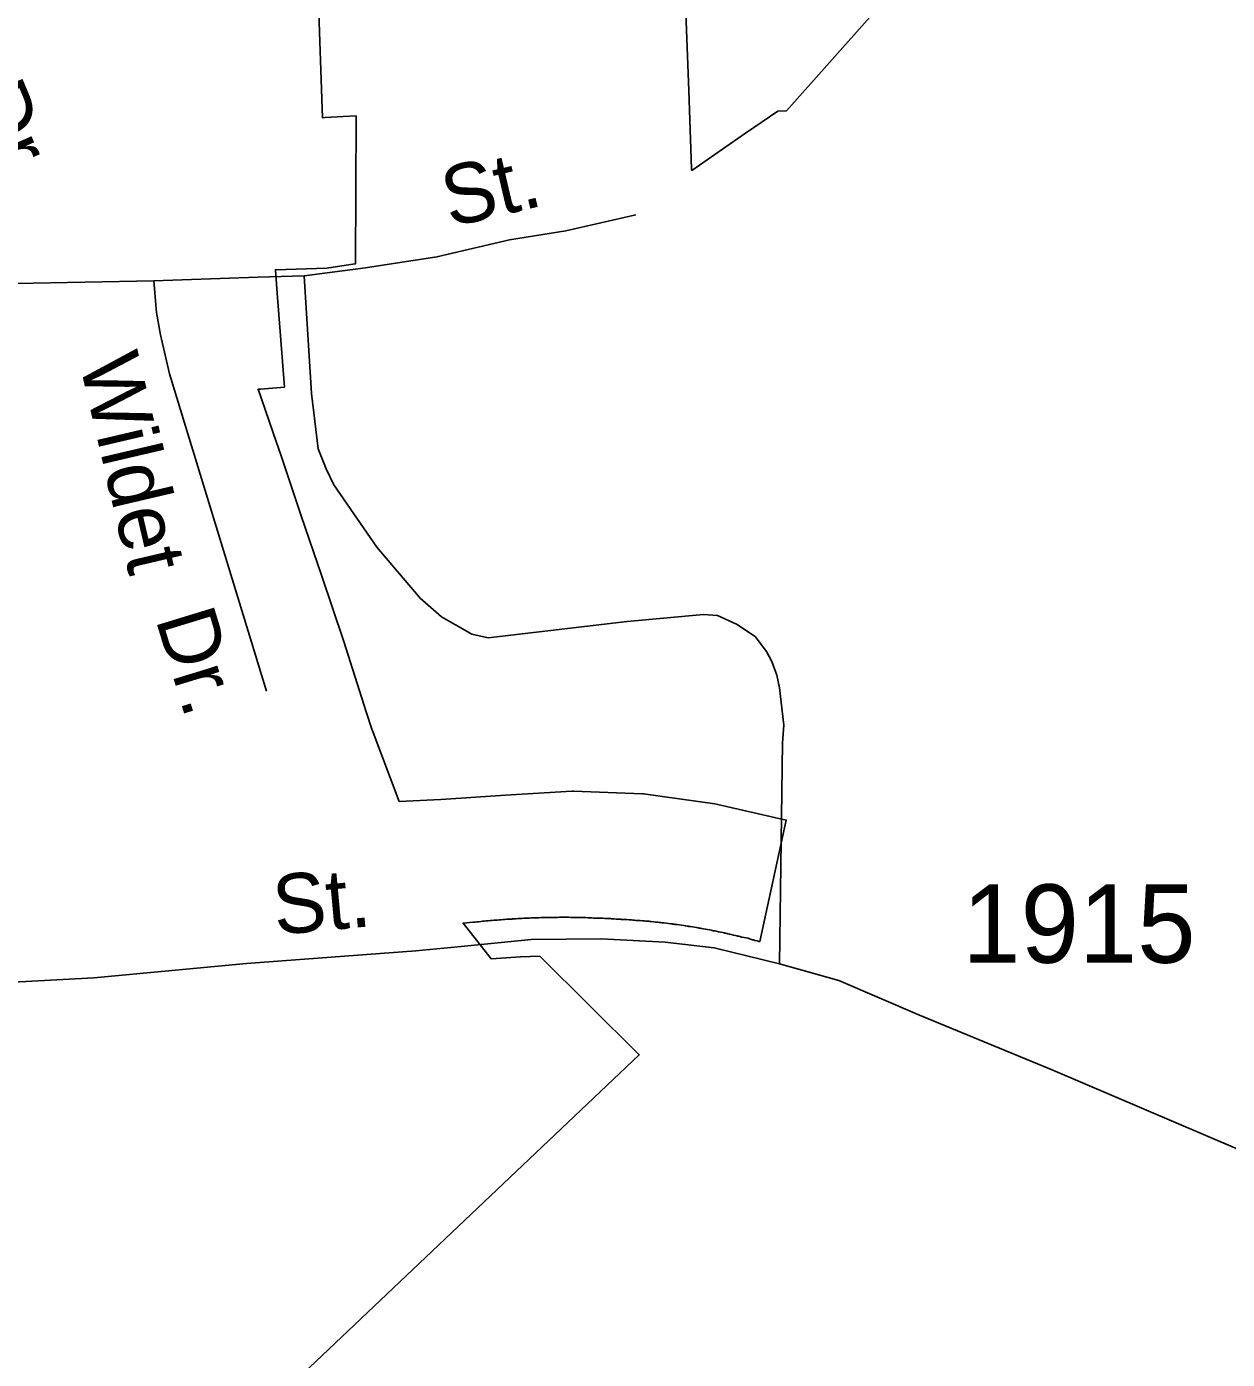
# Model space of a CAD drawing. Extents: x 2220236 to 2384410, y 720751 to 894131.
# Drawn here: x 2265814 to 2267728, y 799079 to 801203 of the extents above; entities that cross this region are included whole.
import ezdxf

# ---------------------------------------------------------------- set-up
doc = ezdxf.new("R2010")
doc.units = 0
doc.layers.add('Default', color=7, linetype='Continuous')

msp = doc.modelspace()

# ---------------------------------------------------------------- linework, layer by layer
at = {"layer": 'Default'}
msp.add_line((2265796.7, 800794), (2266016.6, 800798.2), dxfattribs=at)
for points in [[(2267702.2, 801830.4), (2267025, 801069), (2267011.5, 801068.7), (2266960, 801033.4), (2266874.2, 800974.4), (2266874, 800976.7), (2266869.5, 801101.6), (2266863, 801267.6)], [(2267702.2, 801830.4), (2267025, 801069), (2267011.5, 801068.7), (2266960, 801033.4), (2266874.2, 800974.4), (2266874, 800976.7), (2266869.5, 801101.6), (2266863, 801267.6)], [(2266263.5, 801697.6), (2266285.5, 801058.1), (2266289.8, 801058.4), (2266318.5, 801060.2), (2266339.2, 801061.4)], [(2266263.5, 801697.6), (2266285.5, 801058.1), (2266289.8, 801058.4), (2266318.5, 801060.2), (2266339.2, 801061.4)], [(2266339.2, 801061.4), (2266338.5, 800825.5), (2266337, 800825.2), (2266292.8, 800818.3), (2266210.5, 800816), (2266212.8, 800785.7), (2266225.2, 800629.1), (2266186.8, 800625.9), (2266183, 800625.6), (2266212, 800542.1), (2266220, 800519.6), (2266251.8, 800423.7), (2266284, 800329.1), (2266319.8, 800223.7), (2266355.5, 800111.5), (2266364.5, 800083.8), (2266366.5, 800078.6), (2266408, 799968.6), (2266474.5, 799971.9), (2266577.5, 799978.4), (2266683, 799985.1), (2266686, 799985.2), (2266795.8, 799980.9), (2266797.5, 799980.9), (2266911, 799964.5), (2267024.8, 799938.9), (2266982.5, 799745.1), (2266981.2, 799745.4), (2266978.5, 799746.3), (2266974.5, 799747.2), (2266972.5, 799747.8), (2266971.2, 799748.1), (2266969.5, 799748.6), (2266967.8, 799749.1), (2266966.5, 799749.4), (2266964, 799750.4), (2266961, 799751.1), (2266957.8, 799751.6), (2266954.2, 799752.4), (2266952.2, 799752.9), (2266950.8, 799753.3), (2266949.2, 799753.7), (2266947.5, 799754.1), (2266946.2, 799754.4), (2266944, 799754.9), (2266940.8, 799755.7), (2266937.2, 799756.5), (2266934.8, 799757.1), (2266933.8, 799757.2), (2266931.8, 799757.7), (2266930.5, 799758), (2266928.8, 799758.4), (2266927, 799758.8), (2266925.8, 799759), (2266923.5, 799759.5), (2266920.2, 799760.2), (2266916.8, 799760.9), (2266913.2, 799761.6), (2266911, 799762.1), (2266909.8, 799762.3), (2266908.2, 799762.6), (2266906.5, 799763), (2266905.2, 799763.2), (2266903, 799763.7), (2266899.5, 799764.3), (2266896, 799764.9), (2266892.8, 799765.6), (2266890.5, 799766), (2266889.2, 799766.2), (2266887.8, 799766.4), (2266885.8, 799766.8), (2266884.5, 799767), (2266882.2, 799767.4), (2266878.8, 799768), (2266875.5, 799768.6), (2266872, 799769.1), (2266869.8, 799769.5), (2266868.5, 799769.7), (2266866.8, 799769.9), (2266865, 799770.2), (2266863.8, 799770.4), (2266861.5, 799770.8), (2266858, 799771.2), (2266854.8, 799771.8), (2266851.2, 799772.2), (2266849, 799772.5), (2266847.8, 799772.7), (2266846, 799772.9), (2266844.2, 799773.2), (2266843, 799773.3), (2266840.8, 799773.6), (2266837.2, 799774.1), (2266833.8, 799774.5), (2266830.2, 799774.9), (2266828, 799775.2), (2266826.8, 799775.3), (2266825, 799775.5), (2266823.5, 799775.7), (2266822.2, 799775.8), (2266820, 799776.1)], [(2266339.2, 801061.4), (2266338.5, 800825.5), (2266337, 800825.2), (2266292.8, 800818.3), (2266210.5, 800816), (2266212.8, 800785.7), (2266225.2, 800629.1), (2266186.8, 800625.9), (2266183, 800625.6), (2266212, 800542.1), (2266220, 800519.6), (2266251.8, 800423.7), (2266284, 800329.1), (2266319.8, 800223.7), (2266355.5, 800111.5), (2266364.5, 800083.8), (2266366.5, 800078.6), (2266408, 799968.6), (2266474.5, 799971.9), (2266577.5, 799978.4), (2266683, 799985.1), (2266686, 799985.2), (2266795.8, 799980.9), (2266797.5, 799980.9), (2266911, 799964.5), (2267024.8, 799938.9), (2266982.5, 799745.1), (2266981.2, 799745.4), (2266978.5, 799746.3), (2266974.5, 799747.2), (2266972.5, 799747.8), (2266971.2, 799748.1), (2266969.5, 799748.6), (2266967.8, 799749.1), (2266966.5, 799749.4), (2266964, 799750.4), (2266961, 799751.1), (2266957.8, 799751.6), (2266954.2, 799752.4), (2266952.2, 799752.9), (2266950.8, 799753.3), (2266949.2, 799753.7), (2266947.5, 799754.1), (2266946.2, 799754.4), (2266944, 799754.9), (2266940.8, 799755.7), (2266937.2, 799756.5), (2266934.8, 799757.1), (2266933.8, 799757.2), (2266931.8, 799757.7), (2266930.5, 799758), (2266928.8, 799758.4), (2266927, 799758.8), (2266925.8, 799759), (2266923.5, 799759.5), (2266920.2, 799760.2), (2266916.8, 799760.9), (2266913.2, 799761.6), (2266911, 799762.1), (2266909.8, 799762.3), (2266908.2, 799762.6), (2266906.5, 799763), (2266905.2, 799763.2), (2266903, 799763.7), (2266899.5, 799764.3), (2266896, 799764.9), (2266892.8, 799765.6), (2266890.5, 799766), (2266889.2, 799766.2), (2266887.8, 799766.4), (2266885.8, 799766.8), (2266884.5, 799767), (2266882.2, 799767.4), (2266878.8, 799768), (2266875.5, 799768.6), (2266872, 799769.1), (2266869.8, 799769.5), (2266868.5, 799769.7), (2266866.8, 799769.9), (2266865, 799770.2), (2266863.8, 799770.4), (2266861.5, 799770.8), (2266858, 799771.2), (2266854.8, 799771.8), (2266851.2, 799772.2), (2266849, 799772.5), (2266847.8, 799772.7), (2266846, 799772.9), (2266844.2, 799773.2), (2266843, 799773.3), (2266840.8, 799773.6), (2266837.2, 799774.1), (2266833.8, 799774.5), (2266830.2, 799774.9), (2266828, 799775.2), (2266826.8, 799775.3), (2266825, 799775.5), (2266823.5, 799775.7), (2266822.2, 799775.8), (2266820, 799776.1)], [(2266256.4, 800806.4), (2266354.3, 800819.2), (2266468, 800836.3), (2266583.7, 800863.5), (2266673.6, 800878.2), (2266785.3, 800903.3)], [(2266016.6, 800798.2), (2266182.8, 800803.9), (2266256.4, 800806.4)], [(2266256.4, 800806.4), (2266268.2, 800618.7), (2266278.9, 800530.7), (2266291.3, 800498.8), (2266303.5, 800473), (2266372.5, 800373.6), (2266441.2, 800292.4), (2266475.3, 800262.7), (2266523.6, 800235.1), (2266549.6, 800229.4), (2266771.3, 800255.4), (2266893.1, 800266.6), (2266915.2, 800264.8), (2266945.4, 800251.2), (2266975.5, 800231.4), (2266993.6, 800207.6), (2267001.9, 800191.6), (2267010, 800169.7), (2267014.2, 800149.8), (2267020.8, 800089.9), (2267019, 800061.9), (2267014.3, 799709.9)], [(2266016.6, 800798.2), (2266021.1, 800748.1), (2266027.4, 800712.2), (2266041.9, 800650.3), (2266196.6, 800144.1)], [(2266813, 799776.8), (2266809.5, 799777.2), (2266807.2, 799777.4), (2266806, 799777.5), (2266804.2, 799777.7), (2266802.5, 799777.8), (2266801.2, 799777.9), (2266799, 799778.1), (2266795.5, 799778.4), (2266792, 799778.7), (2266788.5, 799779), (2266785.5, 799778.8), (2266783.2, 799779.2), (2266781.5, 799779.5), (2266780.2, 799779.6), (2266778, 799779.8), (2266774.5, 799780), (2266771, 799780.2), (2266768.5, 799780.3), (2266767.5, 799780.4), (2266765.5, 799780.5), (2266764, 799780.6), (2266762.5, 799780.6), (2266760.5, 799780.8), (2266759.5, 799780.8), (2266756.5, 799781), (2266753.5, 799781.2), (2266750.5, 799781.4), (2266746.5, 799781.6), (2266744.5, 799781.8), (2266743, 799781.9), (2266741.5, 799781.8), (2266739.8, 799782), (2266738.5, 799781.8), (2266735.5, 799782.2), (2266732.5, 799782.4), (2266729.5, 799782.5), (2266726.5, 799782.6), (2266723.5, 799782.8), (2266722.2, 799782.8), (2266720.5, 799782.6), (2266718.5, 799782.4), (2266717.5, 799782.6), (2266714.5, 799783.1), (2266711.5, 799783.2), (2266708.5, 799783.3), (2266705.5, 799783.4), (2266702.5, 799783.4), (2266699.5, 799783.6), (2266696.5, 799783.6), (2266693.5, 799783.7), (2266690.5, 799783.7), (2266687.5, 799783.8), (2266686, 799783.8), (2266684.5, 799783.8), (2266681.5, 799783.8), (2266678.5, 799783.9), (2266675.5, 799783.9), (2266672.5, 799783.9), (2266669.5, 799783.9), (2266666.5, 799783.9), (2266663.5, 799783.9), (2266660.5, 799783.8), (2266657.5, 799783.8), (2266654.5, 799783.8), (2266651.5, 799783.8), (2266648.5, 799783.7), (2266645.5, 799783.6), (2266642.5, 799783.6), (2266639.5, 799783.5), (2266636.5, 799783.4), (2266633.5, 799783.4), (2266630.5, 799783.3), (2266627.5, 799783.2), (2266624.5, 799783.1), (2266621.5, 799783), (2266618.5, 799782.9), (2266615.5, 799782.8), (2266612.5, 799782.6), (2266609.5, 799782.5), (2266606.5, 799782.3), (2266603.5, 799782.2), (2266600.5, 799782.1), (2266597.5, 799781.9), (2266594.5, 799781.7), (2266591.5, 799781.6), (2266588.5, 799781.4), (2266587.2, 799781.2), (2266585.5, 799781.2), (2266582.5, 799780.9), (2266579.5, 799780.8), (2266576.5, 799780.6), (2266573.5, 799780.3), (2266570.5, 799780.1), (2266567.5, 799779.9), (2266564.5, 799779.6), (2266561.5, 799779.4), (2266558.5, 799779.1), (2266555.5, 799778.9), (2266552.8, 799778.6)], [(2266813, 799776.8), (2266809.5, 799777.2), (2266807.2, 799777.4), (2266806, 799777.5), (2266804.2, 799777.7), (2266802.5, 799777.8), (2266801.2, 799777.9), (2266799, 799778.1), (2266795.5, 799778.4), (2266792, 799778.7), (2266788.5, 799779), (2266785.5, 799778.8), (2266783.2, 799779.2), (2266781.5, 799779.5), (2266780.2, 799779.6), (2266778, 799779.8), (2266774.5, 799780), (2266771, 799780.2), (2266768.5, 799780.3), (2266767.5, 799780.4), (2266765.5, 799780.5), (2266764, 799780.6), (2266762.5, 799780.6), (2266760.5, 799780.8), (2266759.5, 799780.8), (2266756.5, 799781), (2266753.5, 799781.2), (2266750.5, 799781.4), (2266746.5, 799781.6), (2266744.5, 799781.8), (2266743, 799781.9), (2266741.5, 799781.8), (2266739.8, 799782), (2266738.5, 799781.8), (2266735.5, 799782.2), (2266732.5, 799782.4), (2266729.5, 799782.5), (2266726.5, 799782.6), (2266723.5, 799782.8), (2266722.2, 799782.8), (2266720.5, 799782.6), (2266718.5, 799782.4), (2266717.5, 799782.6), (2266714.5, 799783.1), (2266711.5, 799783.2), (2266708.5, 799783.3), (2266705.5, 799783.4), (2266702.5, 799783.4), (2266699.5, 799783.6), (2266696.5, 799783.6), (2266693.5, 799783.7), (2266690.5, 799783.7), (2266687.5, 799783.8), (2266686, 799783.8), (2266684.5, 799783.8), (2266681.5, 799783.8), (2266678.5, 799783.9), (2266675.5, 799783.9), (2266672.5, 799783.9), (2266669.5, 799783.9), (2266666.5, 799783.9), (2266663.5, 799783.9), (2266660.5, 799783.8), (2266657.5, 799783.8), (2266654.5, 799783.8), (2266651.5, 799783.8), (2266648.5, 799783.7), (2266645.5, 799783.6), (2266642.5, 799783.6), (2266639.5, 799783.5), (2266636.5, 799783.4), (2266633.5, 799783.4), (2266630.5, 799783.3), (2266627.5, 799783.2), (2266624.5, 799783.1), (2266621.5, 799783), (2266618.5, 799782.9), (2266615.5, 799782.8), (2266612.5, 799782.6), (2266609.5, 799782.5), (2266606.5, 799782.3), (2266603.5, 799782.2), (2266600.5, 799782.1), (2266597.5, 799781.9), (2266594.5, 799781.7), (2266591.5, 799781.6), (2266588.5, 799781.4), (2266587.2, 799781.2), (2266585.5, 799781.2), (2266582.5, 799780.9), (2266579.5, 799780.8), (2266576.5, 799780.6), (2266573.5, 799780.3), (2266570.5, 799780.1), (2266567.5, 799779.9), (2266564.5, 799779.6), (2266561.5, 799779.4), (2266558.5, 799779.1), (2266555.5, 799778.9), (2266552.8, 799778.6)], [(2266552.8, 799778.6), (2266549.8, 799778.4), (2266546.8, 799778.1), (2266543.8, 799777.8), (2266540.8, 799777.5), (2266537.8, 799777.2), (2266534.8, 799776.9), (2266531.8, 799776.6), (2266528.8, 799776.2), (2266525.5, 799775.9), (2266509.8, 799774.7), (2266554.5, 799717.9), (2266601.5, 799721.1), (2266632, 799722.2), (2266790.5, 799564.8), (2266233.5, 799036.5), (2265625.5, 798457.9)], [(2266552.8, 799778.6), (2266549.8, 799778.4), (2266546.8, 799778.1), (2266543.8, 799777.8), (2266540.8, 799777.5), (2266537.8, 799777.2), (2266534.8, 799776.9), (2266531.8, 799776.6), (2266528.8, 799776.2), (2266525.5, 799775.9), (2266509.8, 799774.7), (2266554.5, 799717.9), (2266601.5, 799721.1), (2266632, 799722.2), (2266790.5, 799564.8), (2266233.5, 799036.5), (2265625.5, 798457.9)], [(2266820, 799776.1), (2266816.5, 799776.4), (2266813, 799776.8)], [(2266820, 799776.1), (2266816.5, 799776.4), (2266813, 799776.8)], [(2267839.1, 799373.9), (2267449.7, 799540.2), (2267237, 799628.1), (2267108.6, 799683), (2267014.3, 799709.9), (2266910.1, 799735), (2266832.1, 799744.3), (2266730, 799749.4), (2266618.3, 799748.3), (2266501.5, 799737), (2266434.3, 799730.5), (2266164.8, 799710.1), (2265921, 799687.7), (2265743.3, 799678)]]:
    msp.add_lwpolyline(points, dxfattribs=at)

# ---------------------------------------------------------------- texts
for s, rotation, p in [('Dr.', 292.7203, (2265715.9, 801093.1)), ('St.', 13.2287, (2266488.7, 800883.3)), ('Wildet', 283.185, (2265897.6, 800669.8)), ('Dr.', 286.9935, (2266019, 800259.7)), ('St.', 5.2491, (2266210.9, 799755.7))]:
    msp.add_text(s, height=95, rotation=rotation, dxfattribs=at).set_placement(p)
msp.add_text('1915', height=125, dxfattribs=at).set_placement((2267305.4, 799711.4))

doc.saveas('drawing.dxf')
